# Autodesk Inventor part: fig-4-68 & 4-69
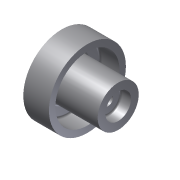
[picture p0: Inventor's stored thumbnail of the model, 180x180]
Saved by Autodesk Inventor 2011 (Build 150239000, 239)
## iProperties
Shininess: 64.0
Length Units: 11269
Angle Units: 11279
Time Units: 11290
Mass Units: 11283
Length Display Precision: 3
Angle Display Precision: 2
Compacted: True
Part Number: fig-4-68 & 4-69
Document SubType Name: Modeling
Created: 2002-12
Designer: deepak
Density: 1 g/cm^3
Density: 0.0
Volumn: 0.0
Area: 0.0
PropertySet Name: Model Information
Control State: 0
Master: False
Checked Out: False
Author: deepak
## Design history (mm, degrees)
sketch "Sketch1"
  geometry: L1 (-8.654, -8.338)-(13.346, -8.338); L2 (13.346, -8.338)-(13.346, 21.662); L3 (13.346, 21.662)-(-6.654, 21.662); L4 (-6.654, 21.662)-(-6.654, 16.662); L5 (-6.654, 16.662)-(6.846, 16.662); L6 (8.346, 15.162)-(8.346, 9.162); L7 (6.846, 7.662)-(-30.654, 7.662); L8 (-30.654, 7.662)-(-30.654, 1.662); L9 (-30.654, 1.662)-(-24.154, 1.662); L10 (-22.654, 0.162)-(-22.654, -4.338); L11 (-22.654, -4.338)-(-8.654, -4.338); L12 (-8.654, -4.338)-(-8.654, -8.338); A1 r 1.5 centre (-24.154, 0.162) between (-22.654, 0.162) and (-24.154, 1.662); A2 r 1.5 centre (6.846, 15.162) between (8.346, 15.162) and (6.846, 16.662); A3 r 1.5 centre (6.846, 9.162) between (6.846, 7.662) and (8.346, 9.162)
  constraints: 24 end point, 10 parallel, 6 point on circle, 6 tangent, 3 centre point, 2 equal radius, 1 horizontal, 1 perpendicular
  dimensions: "d0" = 60 diameter of L3 L1; "d1" = 50 diameter of L5 L1; "d2" = 32 diameter of L7 L1; "d3" = 20 diameter of L9 L1; "d4" = 8 diameter of L11 L1; "d5" = 20 distance of L2.end L3.end; "d6" = 5 distance between parallel lines of L2 L6; "d7" = 22 distance of L1.start L1.end; "d8" = 36 distance between parallel lines of L2 L10; "d9" = 44 distance between parallel lines of L8 L2; "d10" = 1.5 radius of A1
revolve "Revolution1" sketch "Sketch1" stored, may be unused: angle "d11" = 90 deg
body "Solid1"
